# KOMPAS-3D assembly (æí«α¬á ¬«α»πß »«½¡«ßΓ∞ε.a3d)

Referenced files in D:\МОДЕЛЬ ТАНКА Т90\СБОРКИ\СБОРКА ЛИТЬЕ СТАРАЯ\: Сборка корпус с ходовой.a3d, Сборка полка надгусеничная левая.a3d, Сборка полка надгусеничная правая.a3d
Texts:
  Сборка корпус полностью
